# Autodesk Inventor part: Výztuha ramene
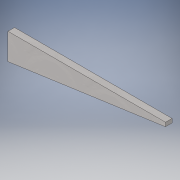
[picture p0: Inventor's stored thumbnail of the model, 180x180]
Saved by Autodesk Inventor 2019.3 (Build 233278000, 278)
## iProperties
Created: 2019-02
Part Number: Výztuha ramene
Material: Ocel, měkká, svařovaná
Document SubType Name: Modeling
Designer: B-hon
Density: 7.85 g/cm^3
Appearance: Svar – měkká ocel
Mass: 226.08 g
Surface Area: 104 cm^2
Volume: 28.8 cm^3
Author: B-hon
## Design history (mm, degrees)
sketch "Náčrt1"
  geometry: L1 (120, 17)-(120, 20); L2 (120, 20)-(0, 20); L3 (0, 20)-(0, 0); L4 (0, 0)-(120, 17)
  constraints: 8 end point, 1 parallel
  dimensions: "d0" = 120 distance of L2.end L1.end; "d8" = 3 distance of L1.start L1.end
extrude "Vysunutí1" new body sketch "Náčrt1" distance "d2" = 5; taper "d3" = 0 deg
node "Těleso1"
